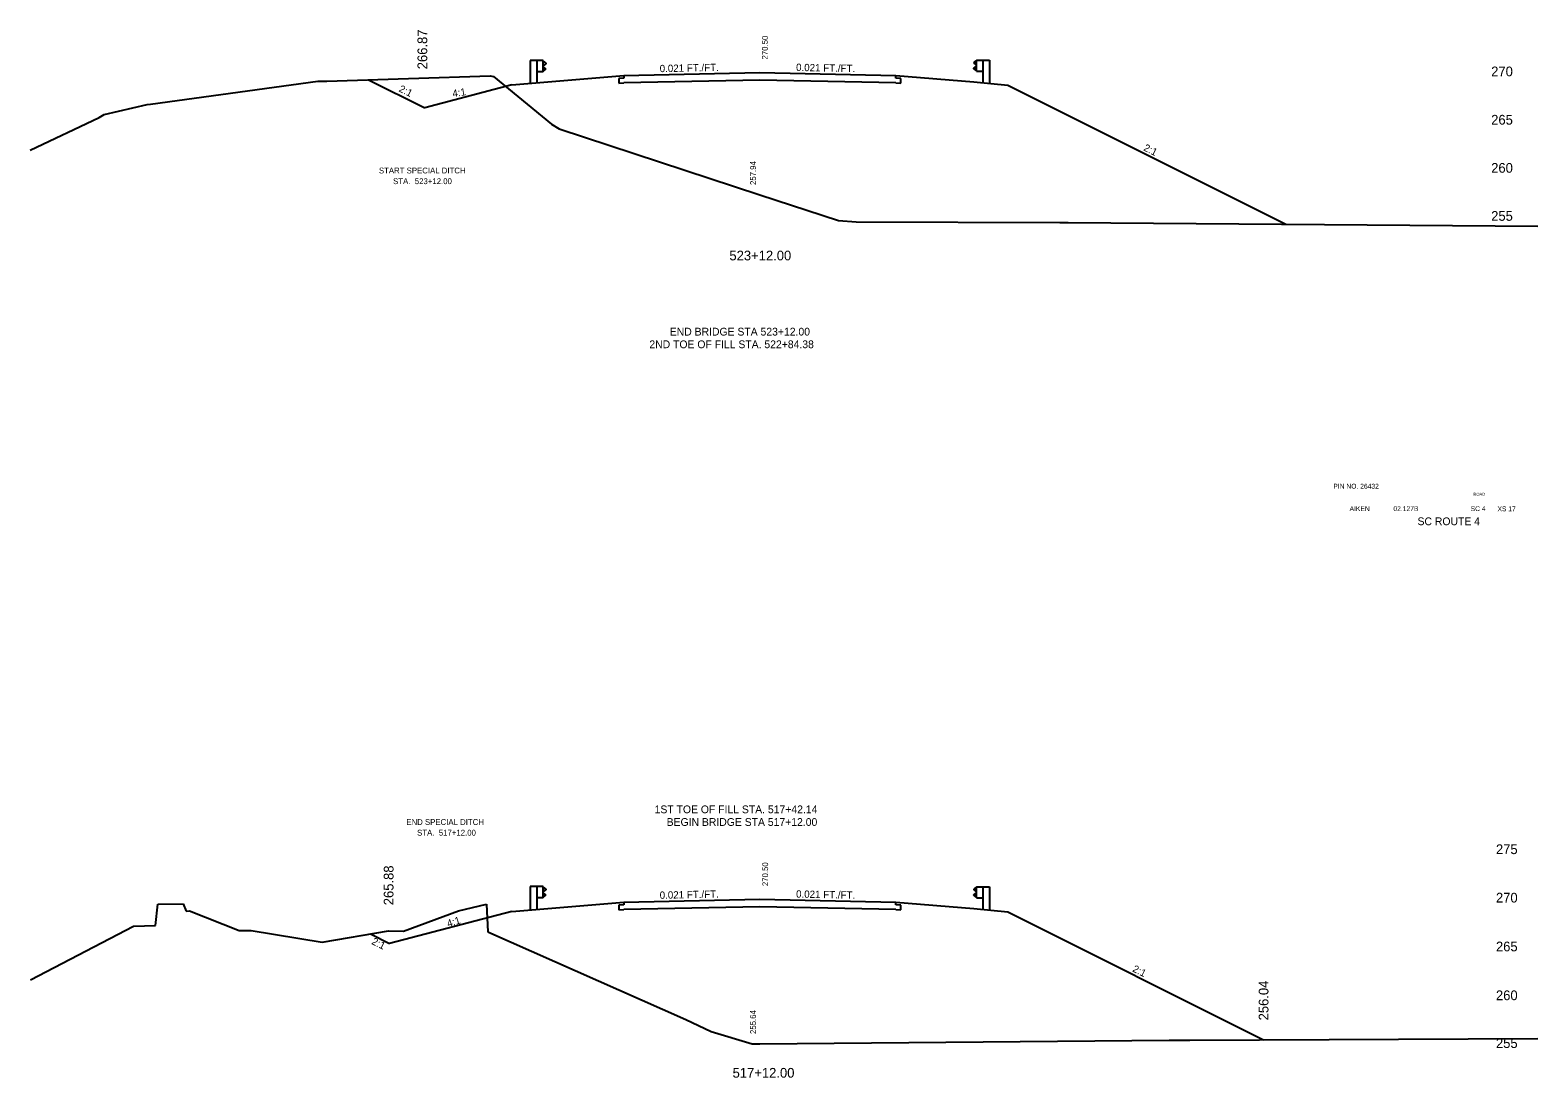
# Model space of a CAD drawing. Extents: x 883 to 1160, y 1002 to 4323.
# Drawn here: x 1005 to 1160, y 2882.1 to 2989.9 of the extents above; entities that cross this region are included whole.
import ezdxf

# ---------------------------------------------------------------- set-up
doc = ezdxf.new("R2010")
doc.units = 0
for name, color, linetype in [('Level 1', 7, 'Continuous'), ('Level 10', 7, 'Continuous'), ('Level 11', 7, 'Continuous'), ('Level 12', 7, 'Continuous'), ('Level 24', 7, 'Continuous'), ('Level 3', 7, 'Continuous'), ('Level 32', 7, 'Continuous'), ('Level 33', 7, 'Continuous'), ('Level 59', 7, 'Continuous'), ('Level 6', 7, 'Continuous'), ('Level 60', 7, 'Continuous'), ('Level 7', 7, 'Continuous')]:
    doc.layers.add(name, color=color, linetype=linetype)

msp = doc.modelspace()

# ---------------------------------------------------------------- linework, layer by layer
at = {"layer": 'Level 11'}
for p, q in [((1066, 2984.91), (1065.5, 2984.9)), ((1065.5, 2984.9), (1065.5, 2984.42)), ((1065.5, 2984.42), (1066, 2984.43)), ((1066, 2985.21), (1066, 2984.91)), ((1094, 2984.91), (1094, 2985.21)), ((1094.5, 2984.9), (1094, 2984.91)), ((1094, 2984.43), (1094.5, 2984.42)), ((1094.5, 2984.42), (1094.5, 2984.9)), ((1066, 2899.91), (1065.5, 2899.9)), ((1065.5, 2899.9), (1065.5, 2899.42)), ((1065.5, 2899.42), (1066, 2899.43)), ((1066, 2900.21), (1066, 2899.91)), ((1094, 2899.91), (1094, 2900.21)), ((1094.5, 2899.9), (1094, 2899.91)), ((1094, 2899.43), (1094.5, 2899.42)), ((1094.5, 2899.42), (1094.5, 2899.9))]:
    msp.add_line(p, q, dxfattribs=at)
at = {"layer": 'Level 12'}
for p, q in [((1080, 2984.72), (1066, 2984.43)), ((1094, 2984.43), (1080, 2984.72)), ((1080, 2899.72), (1066, 2899.43)), ((1094, 2899.43), (1080, 2899.72))]:
    msp.add_line(p, q, dxfattribs=at)
at = {"layer": 'Level 24'}
for p, q in [((1056.4, 2986.74), (1056.4, 2984.33)), ((1057.07, 2986.74), (1056.4, 2986.74)), ((1057.73, 2986.74), (1057.07, 2986.74)), ((1057.07, 2986.74), (1057.07, 2984.39)), ((1057.73, 2985.57), (1057.73, 2986.74)), ((1057.73, 2986.66), (1058, 2986.46)), ((1058, 2986.41), (1057.73, 2986.21)), ((1058, 2985.89), (1057.73, 2986.09)), ((1058, 2986.46), (1058, 2986.41)), ((1058, 2985.84), (1058, 2985.89)), ((1102.27, 2986.72), (1102, 2986.52)), ((1102, 2986.52), (1102, 2986.47)), ((1102, 2986.47), (1102.27, 2986.27)), ((1102, 2985.95), (1102.27, 2986.15)), ((1102, 2985.9), (1102, 2985.95)), ((1102.27, 2985.7), (1102, 2985.9)), ((1102.27, 2985.63), (1102.27, 2986.79)), ((1102.27, 2986.79), (1102.94, 2986.79)), ((1102.94, 2986.79), (1102.94, 2984.45)), ((1102.94, 2986.79), (1103.6, 2986.79)), ((1103.6, 2986.79), (1103.6, 2984.38)), ((1057.73, 2985.57), (1057.07, 2985.57)), ((1057.73, 2985.64), (1058, 2985.84)), ((1102.27, 2985.63), (1102.94, 2985.63)), ((1056.4, 2901.8), (1056.4, 2899.39)), ((1057.07, 2901.8), (1056.4, 2901.8)), ((1057.73, 2901.8), (1057.07, 2901.8)), ((1057.07, 2901.8), (1057.07, 2899.46)), ((1057.73, 2900.63), (1057.07, 2900.63)), ((1057.73, 2900.63), (1057.73, 2901.8)), ((1057.73, 2901.73), (1058, 2901.53)), ((1058, 2901.48), (1057.73, 2901.28)), ((1058, 2900.96), (1057.73, 2901.16)), ((1057.73, 2900.71), (1058, 2900.91)), ((1058, 2901.53), (1058, 2901.48)), ((1058, 2900.91), (1058, 2900.96)), ((1102.27, 2901.72), (1102, 2901.52)), ((1102, 2901.52), (1102, 2901.47)), ((1102, 2901.47), (1102.27, 2901.27)), ((1102, 2900.95), (1102.27, 2901.15)), ((1102, 2900.9), (1102, 2900.95)), ((1102.27, 2900.7), (1102, 2900.9)), ((1102.27, 2900.63), (1102.27, 2901.79)), ((1102.27, 2901.79), (1102.94, 2901.79)), ((1102.94, 2901.79), (1102.94, 2899.45)), ((1102.94, 2901.79), (1103.6, 2901.79)), ((1103.6, 2901.79), (1103.6, 2899.38)), ((1102.27, 2900.63), (1102.94, 2900.63))]:
    msp.add_line(p, q, dxfattribs=at)
at = {"layer": 'Level 59'}
for p, q in [((1066, 2985.21), (1080, 2985.5)), ((1080, 2985.5), (1094, 2985.21)), ((1066, 2900.21), (1080, 2900.5)), ((1080, 2900.5), (1094, 2900.21))]:
    msp.add_line(p, q, dxfattribs=at)
at = {"layer": 'Level 6'}
for p, q in [((1054.5, 2984.25), (1066, 2985.21)), ((1094, 2985.21), (1102, 2984.54)), ((1102, 2984.54), (1105.5, 2984.19)), ((1054.5, 2899.25), (1066, 2900.21)), ((1094, 2900.21), (1102, 2899.54)), ((1102, 2899.54), (1105.5, 2899.19))]:
    msp.add_line(p, q, dxfattribs=at)
at = {"layer": 'Level 60'}
for p, q in [((1017.33, 2982.26), (1034.54, 2984.62)), ((1034.54, 2984.62), (1035, 2984.63)), ((1035, 2984.63), (1035.46, 2984.62)), ((1035.46, 2984.62), (1052.27, 2985.15)), ((1052.27, 2985.15), (1052.63, 2985.1)), ((1052.63, 2985.1), (1058.57, 2980.18)), ((1012.58, 2981.2), (1017, 2982.21)), ((1017, 2982.21), (1017.33, 2982.26)), ((1004.97, 2977.53), (1012.08, 2980.89)), ((1012.08, 2980.89), (1012.58, 2981.2)), ((1058.57, 2980.18), (1059.36, 2979.73)), ((1059.36, 2979.73), (1080, 2972.94)), ((1080, 2972.94), (1088.09, 2970.28)), ((1088.09, 2970.28), (1089.92, 2970.14)), ((1089.92, 2970.14), (1110.86, 2970.07)), ((1110.86, 2970.07), (1111.7, 2970.07)), ((1111.7, 2970.07), (1160, 2969.72)), ((1017.85, 2897.81), (1018.09, 2900)), ((1018.09, 2900), (1020.7, 2900.04)), ((1020.7, 2900.04), (1021, 2899.28)), ((1021, 2899.28), (1021.37, 2899.3)), ((1021.37, 2899.3), (1026.47, 2897.29)), ((1043.37, 2897.23), (1049, 2899.3)), ((1049, 2899.3), (1051.88, 2899.98)), ((1051.88, 2899.98), (1052.04, 2897.16)), ((1005.02, 2892.21), (1015.59, 2897.74)), ((1015.59, 2897.74), (1017.85, 2897.81)), ((1026.47, 2897.29), (1027.71, 2897.27)), ((1027.71, 2897.27), (1035, 2896.08)), ((1035, 2896.08), (1041.83, 2897.26)), ((1041.83, 2897.26), (1043.37, 2897.23)), ((1052.04, 2897.16), (1072.4, 2888.12)), ((1072.4, 2888.12), (1075.01, 2886.89)), ((1075.01, 2886.89), (1079.21, 2885.63)), ((1079.21, 2885.63), (1080, 2885.64)), ((1080, 2885.64), (1122.09, 2886.02)), ((1122.09, 2886.02), (1122.73, 2886.02)), ((1122.73, 2886.02), (1124.2, 2886)), ((1124.2, 2886), (1160, 2886.19))]:
    msp.add_line(p, q, dxfattribs=at)
at = {"layer": 'Level 7'}
for p, q in [((1039.75, 2984.75), (1045.54, 2981.86)), ((1054.5, 2984.25), (1045.54, 2981.86)), ((1105.5, 2984.19), (1134.07, 2969.91)), ((1054.5, 2899.25), (1041.91, 2895.96)), ((1105.5, 2899.19), (1131.8, 2886.04)), ((1039.96, 2896.94), (1041.91, 2895.96))]:
    msp.add_line(p, q, dxfattribs=at)

# ---------------------------------------------------------------- texts
at = {"layer": 'Level 1'}
for s, height, p in [('523+12.00', 1, (1076.87, 2966.19)), ('END BRIDGE STA 523+12.00', 0.8, (1070.74, 2958.46)), ('2ND TOE OF FILL STA. 522+84.38', 0.8, (1068.64, 2957.16)), ('PIN NO. 26432', 0.5, (1138.97, 2942.72)), ('AIKEN', 0.5, (1140.64, 2940.41)), ('02.127B', 0.5, (1145.15, 2940.41)), ('SC ROUTE 4', 0.8, (1147.63, 2938.96)), ('SC 4', 0.5, (1153.09, 2940.41)), ('XS 17', 0.5, (1155.85, 2940.39)), ('1ST TOE OF FILL STA. 517+42.14', 0.8, (1069.18, 2909.34)), ('BEGIN BRIDGE STA 517+12.00', 0.8, (1070.42, 2908.04)), ('517+12.00', 1, (1077.2, 2882.15))]:
    msp.add_text(s, height=height, dxfattribs=at).set_placement(p)
at = {"layer": 'Level 10'}
for s, p in [('257.94', (1079.6, 2973.94)), ('255.64', (1079.6, 2886.64))]:
    msp.add_text(s, height=0.6, rotation=90, dxfattribs=at).set_placement(p)
at = {"layer": 'Level 3'}
for s, height, p in [(' 270', 1, (1154.83, 2985.12)), (' 265', 1, (1154.83, 2980.15)), (' 260', 1, (1154.83, 2975.2)), (' 255', 1, (1154.83, 2970.26)), ('ROAD', 0.3, (1153.38, 2941.99)), (' 275', 1, (1155.32, 2905.14)), (' 270', 1, (1155.32, 2900.16)), (' 265', 1, (1155.32, 2895.14)), (' 260', 1, (1155.32, 2890.12)), (' 255', 1, (1155.32, 2885.2))]:
    msp.add_text(s, height=height, dxfattribs=at).set_placement(p)
at = {"layer": 'Level 32'}
for s, rotation, p in [('0.021 FT./FT.', 1.1916, (1069.71, 2985.54)), ('0.021 FT./FT.', 358.8084, (1083.72, 2985.67)), ('2:1', 333.435, (1042.81, 2983.59)), ('4:1', 9.4623, (1048.45, 2982.96)), ('2:1', 333.435, (1119.39, 2977.53)), ('0.021 FT./FT.', 1.1916, (1069.71, 2900.54)), ('0.021 FT./FT.', 358.8084, (1083.72, 2900.67)), ('4:1', 17.8076, (1047.96, 2897.61)), ('2:1', 333.435, (1040.01, 2895.92)), ('2:1', 333.435, (1118.25, 2893.1))]:
    msp.add_text(s, height=0.75, rotation=rotation, dxfattribs=at).set_placement(p)
for s, p in [('START SPECIAL DITCH', (1040.83, 2975.13)), ('STA.  523+12.00', (1042.29, 2974.03)), ('END SPECIAL DITCH', (1043.65, 2908.14)), ('STA.  517+12.00', (1044.76, 2907.04))]:
    msp.add_text(s, height=0.6, dxfattribs=at).set_placement(p)
at = {"layer": 'Level 33'}
for s, p in [('266.87', (1045.8, 2985.84)), ('265.88', (1042.33, 2899.88)), ('256.04', (1132.3, 2888.04))]:
    msp.add_text(s, height=1, rotation=90, dxfattribs=at).set_placement(p)
at = {"layer": 'Level 59'}
for p in [(1080.82, 2986.62), (1080.85, 2901.62)]:
    msp.add_text(' 270.50', height=0.6, rotation=90, dxfattribs=at).set_placement(p)

doc.saveas('drawing.dxf')
